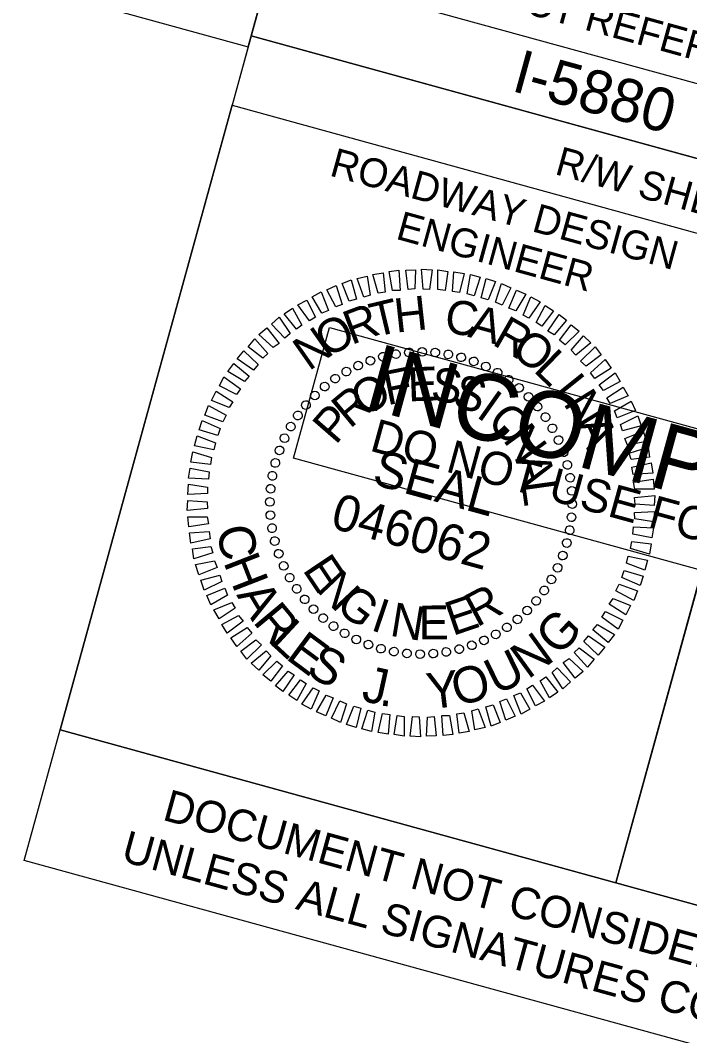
# Model space of a CAD drawing. Extents: x 1641063 to 2864602, y 841295 to 973236.
# Drawn here: x 1642843.9 to 1642960, y 842189.2 to 842365.5 of the extents above; entities that cross this region are included whole.
import ezdxf

# ---------------------------------------------------------------- set-up
doc = ezdxf.new("R2010")
doc.units = 0
for name, color, linetype in [('Default', 7, 'Continuous'), ('Old_Level_1', 7, 'Continuous'), ('Prop CMT Concrete Structures', 7, 'Continuous'), ('Prop CMT Guardrail Widen Shoulder', 7, 'Continuous'), ('Prop CMT Shoulder Point', 7, 'Continuous'), ('Prop DSN Text', 7, 'Continuous'), ('Prop Easement Construction', 7, 'Continuous')]:
    doc.layers.add(name, color=color, linetype=linetype)

msp = doc.modelspace()

# ---------------------------------------------------------------- linework, layer by layer
at = {"layer": 'Old_Level_1'}
msp.add_lwpolyline([(1642891.27, 842289.47), (1642897.51, 842312.13), (1643039.24, 842273.13), (1643033, 842250.47)], close=True, dxfattribs=at)
at = {"layer": 'Prop CMT Concrete Structures'}
for p, q in [((1642887.23, 842374.88), (1643080.1, 842321.79)), ((1642883.91, 842362.79), (1642880.6, 842350.75)), ((1642883.91, 842362.79), (1643076.79, 842309.74)), ((1642883.91, 842362.79), (1643076.79, 842309.74)), ((1642977.06, 842324.21), (1642947.23, 842215.77))]:
    msp.add_line(p, q, dxfattribs=at)
for points in [[(1641358.6, 841719.52), (1641637.16, 842731.87), (1642890.57, 842386.98), (1642850.76, 842242.29), (1643043.63, 842189.2), (1642804.85, 841321.52)], [(1642890.57, 842386.98), (1643083.47, 842333.88), (1643076.79, 842309.74), (1642883.91, 842362.79)], [(1642880.6, 842350.75), (1642977.06, 842324.21), (1642947.21, 842215.73), (1642850.76, 842242.29)], [(1642977.06, 842324.21), (1643073.47, 842297.69), (1643043.63, 842189.2), (1642947.21, 842215.73)]]:
    msp.add_lwpolyline(points, close=True, dxfattribs=at)
at = {"layer": 'Prop CMT Guardrail Widen Shoulder'}
msp.add_lwpolyline([(1642738.73, 842400.68), (1642883.38, 842360.88), (1642890.57, 842386.98), (1642745.92, 842426.79)], close=True, dxfattribs=at)
at = {"layer": 'Prop DSN Text'}
for p, q in [((1642844.53, 842219.63), (1642850.76, 842242.29)), ((1642844.53, 842219.63), (1642850.76, 842242.29)), ((1642850.76, 842242.29), (1643043.63, 842189.22)), ((1642850.76, 842242.29), (1643043.63, 842189.22)), ((1643037.4, 842166.56), (1642844.53, 842219.63)), ((1643037.4, 842166.56), (1642844.53, 842219.63))]:
    msp.add_line(p, q, dxfattribs=at)
at = {"layer": 'Prop Easement Construction'}
for p, q in [((1642906.8, 842307.08), (1642906.8, 842307.08)), ((1642909.03, 842307.58), (1642909.03, 842307.58)), ((1642911.27, 842307.87), (1642911.27, 842307.87)), ((1642913.55, 842307.94), (1642913.55, 842307.94)), ((1642915.88, 842307.77), (1642915.88, 842307.77)), ((1642918.14, 842307.52), (1642918.14, 842307.52)), ((1642920.38, 842306.99), (1642920.38, 842306.99)), ((1642902.48, 842305.59), (1642902.48, 842305.59)), ((1642904.57, 842306.41), (1642904.57, 842306.41)), ((1642922.57, 842306.27), (1642922.57, 842306.27)), ((1642924.66, 842305.36), (1642924.66, 842305.36)), ((1642898.49, 842303.32), (1642898.49, 842303.32)), ((1642900.41, 842304.5), (1642900.41, 842304.5)), ((1642926.67, 842304.36), (1642926.67, 842304.36)), ((1642896.67, 842301.9), (1642896.67, 842301.9)), ((1642928.61, 842303.1), (1642928.61, 842303.1)), ((1642930.4, 842301.67), (1642930.4, 842301.67)), ((1642894.94, 842300.4), (1642894.94, 842300.4)), ((1642932.12, 842300.15), (1642932.12, 842300.15)), ((1642893.42, 842298.69), (1642893.42, 842298.69)), ((1642933.62, 842298.42), (1642933.62, 842298.42)), ((1642891.99, 842296.9), (1642891.99, 842296.9)), ((1642935.04, 842296.59), (1642935.04, 842296.59)), ((1642890.73, 842294.95), (1642890.73, 842294.95)), ((1642936.22, 842294.67), (1642936.22, 842294.67)), ((1642889.73, 842292.94), (1642889.73, 842292.94)), ((1642937.31, 842292.61), (1642937.31, 842292.61)), ((1642888.82, 842290.85), (1642888.82, 842290.85)), ((1642938.12, 842290.51), (1642938.12, 842290.51)), ((1642888.09, 842288.66), (1642888.09, 842288.66)), ((1642938.79, 842288.29), (1642938.79, 842288.29)), ((1642887.57, 842286.42), (1642887.57, 842286.42)), ((1642939.3, 842286.05), (1642939.3, 842286.05)), ((1642887.32, 842284.17), (1642887.32, 842284.17)), ((1642939.59, 842283.82), (1642939.59, 842283.82)), ((1642887.15, 842281.83), (1642887.15, 842281.83)), ((1642913.4, 842281.69), (1642913.4, 842281.69)), ((1642939.65, 842281.54), (1642939.65, 842281.54)), ((1642887.21, 842279.55), (1642887.21, 842279.55)), ((1642939.49, 842279.21), (1642939.49, 842279.21)), ((1642887.5, 842277.32), (1642887.5, 842277.32)), ((1642939.23, 842276.95), (1642939.23, 842276.95)), ((1642888.01, 842275.08), (1642888.01, 842275.08)), ((1642938.71, 842274.71), (1642938.71, 842274.71)), ((1642888.68, 842272.86), (1642888.68, 842272.86)), ((1642937.99, 842272.52), (1642937.99, 842272.52)), ((1642889.49, 842270.76), (1642889.49, 842270.76)), ((1642937.07, 842270.43), (1642937.07, 842270.43)), ((1642890.58, 842268.7), (1642890.58, 842268.7)), ((1642936.07, 842268.42), (1642936.07, 842268.42)), ((1642891.76, 842266.78), (1642891.76, 842266.78)), ((1642934.82, 842266.48), (1642934.82, 842266.48)), ((1642893.19, 842264.95), (1642893.19, 842264.95)), ((1642933.39, 842264.68), (1642933.39, 842264.68)), ((1642894.68, 842263.22), (1642894.68, 842263.22)), ((1642931.87, 842262.97), (1642931.87, 842262.97)), ((1642896.4, 842261.7), (1642896.4, 842261.7)), ((1642930.13, 842261.47), (1642930.13, 842261.47)), ((1642898.19, 842260.27), (1642898.19, 842260.27)), ((1642928.31, 842260.05), (1642928.31, 842260.05)), ((1642900.14, 842259.01), (1642900.14, 842259.01)), ((1642902.15, 842258.01), (1642902.15, 842258.01)), ((1642924.33, 842257.78), (1642924.33, 842257.78)), ((1642926.39, 842258.87), (1642926.39, 842258.87)), ((1642904.23, 842257.1), (1642904.23, 842257.1)), ((1642906.42, 842256.38), (1642906.42, 842256.38)), ((1642908.66, 842255.86), (1642908.66, 842255.86)), ((1642917.77, 842255.79), (1642917.77, 842255.79)), ((1642920.01, 842256.29), (1642920.01, 842256.29)), ((1642922.23, 842256.96), (1642922.23, 842256.96)), ((1642910.92, 842255.6), (1642910.92, 842255.6)), ((1642913.25, 842255.43), (1642913.25, 842255.43)), ((1642915.54, 842255.5), (1642915.54, 842255.5))]:
    msp.add_line(p, q, dxfattribs=at)
for points in [[(1642903.46, 842317.43), (1642902.29, 842320.65), (1642904.07, 842321.06), (1642904.58, 842317.79)], [(1642905.95, 842318.09), (1642905.06, 842321.34), (1642906.81, 842321.65), (1642907.18, 842318.26)], [(1642908.45, 842318.58), (1642907.89, 842321.86), (1642909.56, 842322.08), (1642909.8, 842318.56)], [(1642911.14, 842318.76), (1642910.76, 842322.09), (1642912.44, 842322.15), (1642912.3, 842318.84)], [(1642913.74, 842318.79), (1642913.5, 842322.25), (1642915.31, 842322.17), (1642914.87, 842318.77)], [(1642916.32, 842318.72), (1642916.34, 842322.17), (1642918.05, 842321.9), (1642917.57, 842318.56)], [(1642918.83, 842318.4), (1642919.1, 842321.79), (1642920.87, 842321.55), (1642920.08, 842318.24)], [(1642921.42, 842318.01), (1642922.01, 842321.37), (1642923.67, 842320.89), (1642922.63, 842317.65)], [(1642898.59, 842315.71), (1642897.04, 842318.7), (1642898.68, 842319.42), (1642899.72, 842316.12)], [(1642900.91, 842316.74), (1642899.7, 842319.8), (1642901.26, 842320.43), (1642902.18, 842317.06)], [(1642923.84, 842317.33), (1642924.69, 842320.63), (1642926.34, 842320.15), (1642925.04, 842316.97)], [(1642926.33, 842316.53), (1642927.38, 842319.77), (1642928.97, 842319.04), (1642927.5, 842316.02)], [(1642896.16, 842314.66), (1642894.51, 842317.46), (1642896.04, 842318.37), (1642897.31, 842315.12)], [(1642928.66, 842315.5), (1642929.95, 842318.63), (1642931.56, 842317.95), (1642929.84, 842315.04)], [(1642931.1, 842314.28), (1642932.45, 842317.45), (1642934.07, 842316.6), (1642932.1, 842313.76)], [(1642894.04, 842313.32), (1642891.99, 842316.06), (1642893.55, 842316.9), (1642895.06, 842313.92)], [(1642933.36, 842313), (1642934.93, 842315.95), (1642936.37, 842315.04), (1642934.34, 842312.37)], [(1642889.76, 842310.31), (1642887.47, 842312.74), (1642888.8, 842313.96), (1642890.66, 842311.11)], [(1642891.77, 842311.85), (1642889.65, 842314.5), (1642891.1, 842315.53), (1642892.72, 842312.58)], [(1642935.41, 842311.51), (1642937.39, 842314.4), (1642938.65, 842313.43), (1642936.48, 842310.85)], [(1642887.72, 842308.68), (1642885.27, 842310.92), (1642886.65, 842312.08), (1642888.76, 842309.38)], [(1642937.44, 842309.96), (1642939.47, 842312.62), (1642940.86, 842311.51), (1642938.41, 842309.12)], [(1642939.47, 842308.2), (1642941.58, 842310.73), (1642942.88, 842309.48), (1642940.28, 842307.34)], [(1642885.95, 842306.81), (1642883.38, 842308.82), (1642884.55, 842310.19), (1642886.8, 842307.62)], [(1642941.1, 842306.32), (1642943.62, 842308.8), (1642944.67, 842307.4), (1642942.06, 842305.43)], [(1642884.34, 842304.74), (1642881.49, 842306.71), (1642882.66, 842308.09), (1642885.13, 842305.73)], [(1642882.75, 842302.77), (1642879.84, 842304.49), (1642880.91, 842305.89), (1642883.58, 842303.69)], [(1642942.78, 842304.27), (1642945.37, 842306.57), (1642946.4, 842305.12), (1642943.56, 842303.31)], [(1642881.37, 842300.54), (1642878.4, 842302), (1642879.18, 842303.58), (1642882.05, 842301.5)], [(1642944.31, 842302.21), (1642947.06, 842304.31), (1642947.96, 842302.78), (1642945.07, 842301.2)], [(1642945.67, 842299.97), (1642948.46, 842301.79), (1642949.37, 842300.26), (1642946.23, 842298.96)], [(1642880.09, 842298.27), (1642877.05, 842299.48), (1642877.85, 842301.12), (1642880.76, 842299.23)], [(1642879.02, 842295.8), (1642875.85, 842296.93), (1642876.5, 842298.6), (1642879.58, 842296.95)], [(1642946.98, 842297.69), (1642949.89, 842299.37), (1642950.61, 842297.73), (1642947.43, 842296.49)], [(1642947.99, 842295.32), (1642951.02, 842296.81), (1642951.61, 842295.1), (1642948.35, 842294.2)], [(1642878.14, 842293.43), (1642874.87, 842294.37), (1642875.4, 842296.02), (1642878.55, 842294.62)], [(1642877.44, 842290.91), (1642874.11, 842291.6), (1642874.55, 842293.32), (1642877.75, 842292.12)], [(1642948.78, 842292.91), (1642951.95, 842294.14), (1642952.53, 842292.38), (1642949.23, 842291.71)], [(1642949.52, 842290.34), (1642952.81, 842291.39), (1642953.07, 842289.65), (1642949.88, 842289.22)], [(1642876.84, 842288.36), (1642873.45, 842288.8), (1642873.79, 842290.55), (1642877.05, 842289.61)], [(1642876.52, 842285.85), (1642873.05, 842285.99), (1642873.34, 842287.75), (1642876.63, 842287.12)], [(1642949.98, 842287.9), (1642953.35, 842288.66), (1642953.6, 842286.87), (1642950.2, 842286.66)], [(1642950.28, 842285.29), (1642953.7, 842285.81), (1642953.86, 842284.1), (1642950.51, 842284.1)], [(1642876.35, 842283.31), (1642872.92, 842283.16), (1642873.05, 842284.96), (1642876.32, 842284.45)], [(1642876.34, 842280.72), (1642872.8, 842280.39), (1642872.92, 842282.14), (1642876.26, 842281.87)], [(1642950.46, 842282.65), (1642954, 842282.98), (1642953.88, 842281.23), (1642950.55, 842281.5)], [(1642876.53, 842278.08), (1642873.1, 842277.56), (1642872.94, 842279.27), (1642876.29, 842279.27)], [(1642950.45, 842280.06), (1642953.89, 842280.21), (1642953.75, 842278.41), (1642950.48, 842278.92)], [(1642950.28, 842277.52), (1642953.75, 842277.38), (1642953.46, 842275.62), (1642950.17, 842276.25)], [(1642876.83, 842275.47), (1642873.45, 842274.71), (1642873.21, 842276.5), (1642876.61, 842276.71)], [(1642877.28, 842273.03), (1642873.99, 842271.98), (1642873.73, 842273.72), (1642876.92, 842274.15)], [(1642949.96, 842275.01), (1642953.36, 842274.57), (1642953.02, 842272.82), (1642949.75, 842273.77)], [(1642878.03, 842270.46), (1642874.85, 842269.23), (1642874.28, 842270.99), (1642877.58, 842271.66)], [(1642949.36, 842272.46), (1642952.69, 842271.77), (1642952.25, 842270.05), (1642949.05, 842271.25)], [(1642948.66, 842269.94), (1642951.93, 842269), (1642951.4, 842267.35), (1642948.25, 842268.75)], [(1642878.81, 842268.05), (1642875.78, 842266.56), (1642875.2, 842268.27), (1642878.45, 842269.17)], [(1642879.82, 842265.68), (1642876.91, 842264), (1642876.2, 842265.64), (1642879.37, 842266.88)], [(1642947.78, 842267.58), (1642950.95, 842266.44), (1642950.3, 842264.77), (1642947.22, 842266.43)], [(1642946.72, 842265.1), (1642949.75, 842263.89), (1642948.96, 842262.25), (1642946.04, 842264.14)], [(1642881.13, 842263.4), (1642878.34, 842261.58), (1642877.44, 842263.11), (1642880.58, 842264.41)], [(1642945.43, 842262.83), (1642948.41, 842261.37), (1642947.62, 842259.79), (1642944.76, 842261.87)], [(1642882.5, 842261.16), (1642879.74, 842259.06), (1642878.84, 842260.59), (1642881.73, 842262.17)], [(1642884.02, 842259.1), (1642881.43, 842256.8), (1642880.4, 842258.25), (1642883.24, 842260.06)], [(1642944.05, 842260.6), (1642946.96, 842258.88), (1642945.9, 842257.48), (1642943.22, 842259.68)], [(1642885.71, 842257.05), (1642883.18, 842254.57), (1642882.13, 842255.97), (1642884.75, 842257.94)], [(1642942.47, 842258.63), (1642945.31, 842256.66), (1642944.15, 842255.28), (1642941.67, 842257.64)], [(1642887.33, 842255.17), (1642885.22, 842252.64), (1642883.92, 842253.89), (1642886.52, 842256.03)], [(1642940.86, 842256.56), (1642943.42, 842254.55), (1642942.26, 842253.18), (1642940, 842255.75)], [(1642889.36, 842253.41), (1642887.33, 842250.75), (1642885.94, 842251.86), (1642888.39, 842254.25)], [(1642939.08, 842254.69), (1642941.53, 842252.45), (1642940.15, 842251.29), (1642938.04, 842253.99)], [(1642891.39, 842251.86), (1642889.41, 842248.97), (1642888.15, 842249.94), (1642890.32, 842252.52)], [(1642937.04, 842253.06), (1642939.34, 842250.63), (1642938, 842249.41), (1642936.14, 842252.26)], [(1642893.44, 842250.37), (1642891.87, 842247.42), (1642890.43, 842248.33), (1642892.47, 842251)], [(1642935.03, 842251.52), (1642937.16, 842248.87), (1642935.7, 842247.84), (1642934.09, 842250.79)], [(1642895.7, 842249.09), (1642894.35, 842245.92), (1642892.73, 842246.77), (1642894.7, 842249.61)], [(1642930.64, 842248.71), (1642932.29, 842245.91), (1642930.77, 842245), (1642929.49, 842248.25)], [(1642932.76, 842250.05), (1642934.81, 842247.31), (1642933.25, 842246.47), (1642931.75, 842249.45)], [(1642898.14, 842247.87), (1642896.85, 842244.74), (1642895.25, 842245.42), (1642896.96, 842248.33)], [(1642900.47, 842246.84), (1642899.42, 842243.6), (1642897.83, 842244.33), (1642899.3, 842247.35)], [(1642928.21, 842247.66), (1642929.76, 842244.67), (1642928.12, 842243.96), (1642927.08, 842247.25)], [(1642902.96, 842246.04), (1642902.12, 842242.74), (1642900.46, 842243.22), (1642901.76, 842246.4)], [(1642905.38, 842245.36), (1642904.79, 842242.01), (1642903.13, 842242.48), (1642904.18, 842245.72)], [(1642907.98, 842244.97), (1642907.7, 842241.58), (1642905.93, 842241.82), (1642906.72, 842245.13)], [(1642920.85, 842245.28), (1642921.74, 842242.03), (1642919.99, 842241.72), (1642919.62, 842245.11)], [(1642923.34, 842245.94), (1642924.51, 842242.72), (1642922.74, 842242.31), (1642922.22, 842245.58)], [(1642925.89, 842246.63), (1642927.11, 842243.57), (1642925.54, 842242.94), (1642924.62, 842246.31)], [(1642910.49, 842244.65), (1642910.46, 842241.2), (1642908.75, 842241.47), (1642909.23, 842244.81)], [(1642913.06, 842244.58), (1642913.31, 842241.12), (1642911.49, 842241.2), (1642911.93, 842244.6)], [(1642915.66, 842244.61), (1642916.05, 842241.28), (1642914.36, 842241.22), (1642914.51, 842244.53)], [(1642918.35, 842244.79), (1642918.91, 842241.51), (1642917.24, 842241.3), (1642917.01, 842244.81)]]:
    msp.add_lwpolyline(points, close=True, dxfattribs=at)
for centre, major_axis in [((1642911.29, 842307.83), (-0.061, 0.751)), ((1642913.58, 842307.91), (0.005, 0.753)), ((1642915.86, 842307.8), (0.071, 0.75)), ((1642904.6, 842306.39), (-0.253, 0.709)), ((1642906.78, 842307.06), (-0.19, 0.729)), ((1642909.02, 842307.54), (-0.126, 0.742)), ((1642918.13, 842307.48), (0.136, 0.741)), ((1642920.36, 842306.97), (0.2, 0.726)), ((1642922.54, 842306.27), (0.262, 0.706)), ((1642900.44, 842304.49), (-0.372, 0.655)), ((1642902.48, 842305.53), (-0.314, 0.685)), ((1642924.65, 842305.38), (0.323, 0.68)), ((1642926.67, 842304.31), (0.381, 0.65)), ((1642898.5, 842303.27), (-0.428, 0.62)), ((1642928.59, 842303.07), (0.436, 0.614)), ((1642896.68, 842301.89), (-0.48, 0.58)), ((1642930.4, 842301.66), (0.488, 0.574)), ((1642894.98, 842300.36), (-0.529, 0.536)), ((1642932.07, 842300.11), (0.536, 0.529)), ((1642893.42, 842298.68), (-0.574, 0.488)), ((1642933.61, 842298.41), (0.58, 0.48)), ((1642892.02, 842296.87), (-0.614, 0.436)), ((1642934.99, 842296.58), (0.62, 0.428)), ((1642890.78, 842294.95), (-0.65, 0.381)), ((1642936.2, 842294.65), (0.655, 0.372)), ((1642889.71, 842292.93), (-0.68, 0.323)), ((1642937.25, 842292.61), (0.685, 0.314)), ((1642888.82, 842290.82), (-0.706, 0.262)), ((1642938.11, 842290.49), (0.709, 0.253)), ((1642888.11, 842288.64), (-0.726, 0.2)), ((1642938.78, 842288.3), (0.729, 0.19)), ((1642887.6, 842286.41), (-0.741, 0.136)), ((1642939.26, 842286.07), (0.742, 0.126)), ((1642887.29, 842284.15), (-0.75, 0.071)), ((1642939.54, 842283.79), (0.751, 0.061)), ((1642887.17, 842281.86), (-0.753, 0.005)), ((1642939.63, 842281.51), (0.753, -0.005)), ((1642887.26, 842279.58), (-0.751, -0.061)), ((1642939.51, 842279.22), (0.75, -0.071)), ((1642887.54, 842277.31), (-0.742, -0.126)), ((1642939.2, 842276.96), (0.741, -0.136)), ((1642888.02, 842275.07), (-0.729, -0.19)), ((1642938.69, 842274.73), (0.726, -0.2)), ((1642888.69, 842272.88), (-0.709, -0.253)), ((1642937.99, 842272.55), (0.706, -0.262)), ((1642889.56, 842270.76), (-0.685, -0.314)), ((1642937.1, 842270.44), (0.68, -0.323)), ((1642890.6, 842268.72), (-0.655, -0.372)), ((1642936.03, 842268.42), (0.65, -0.381)), ((1642891.82, 842266.79), (-0.62, -0.428)), ((1642934.78, 842266.5), (0.614, -0.436)), ((1642893.2, 842264.96), (-0.58, -0.48)), ((1642933.38, 842264.69), (0.574, -0.488)), ((1642894.73, 842263.26), (-0.536, -0.529)), ((1642931.82, 842263.01), (0.529, -0.536)), ((1642896.41, 842261.71), (-0.488, -0.574)), ((1642898.21, 842260.3), (-0.436, -0.614)), ((1642928.3, 842260.1), (0.428, -0.62)), ((1642930.12, 842261.48), (0.48, -0.58)), ((1642900.13, 842259.06), (-0.381, -0.65)), ((1642926.36, 842258.88), (0.372, -0.655)), ((1642902.16, 842257.99), (-0.323, -0.68)), ((1642904.26, 842257.1), (-0.262, -0.706)), ((1642922.2, 842256.98), (0.253, -0.709)), ((1642924.32, 842257.84), (0.314, -0.685)), ((1642906.44, 842256.4), (-0.2, -0.726)), ((1642908.67, 842255.89), (-0.136, -0.741)), ((1642910.94, 842255.57), (-0.071, -0.75)), ((1642913.22, 842255.46), (-0.005, -0.753)), ((1642915.51, 842255.54), (0.061, -0.751)), ((1642917.78, 842255.83), (0.126, -0.742)), ((1642920.02, 842256.31), (0.19, -0.729))]:
    msp.add_ellipse(centre, major_axis=major_axis, ratio=0.999708, dxfattribs=at)

# ---------------------------------------------------------------- texts
at = {"layer": 'Default'}
for s, rotation, p in [('C', 281.8134, (1642877.83, 842277.23)), ('H', 291.2571, (1642879.04, 842271.46)), ('A', 301.0969, (1642881.29, 842265.73)), ('R', 309.8096, (1642884.07, 842261.05)), ('G', 46.4133, (1642937.26, 842254.9)), ('L', 317.1818, (1642886.96, 842257.46)), ('E', 323.366, (1642889.72, 842254.75)), ('N', 35.8424, (1642931.94, 842250.98)), ('S', 330.3726, (1642893.18, 842252.06)), ('U', 26.0482, (1642926.45, 842248.27)), ('J', 347.6456, (1642902.88, 842247.39)), ('Y', 6.8561, (1642914.75, 842245.84)), ('O', 14.6548, (1642919.6, 842246.35)), ('.', 352.8275, (1642906.02, 842246.58))]:
    msp.add_text(s, height=6.27, rotation=rotation, dxfattribs=at).set_placement(p)
at = {"layer": 'Old_Level_1'}
for s, height, p in [('INCOMPLETE PLANS', 11.52, (1642903.01, 842298.38)), ('DO NOT USE FOR R/W ACQUISITION', 5.76, (1642904.29, 842290.82))]:
    msp.add_text(s, height=height, rotation=344.6135, dxfattribs=at).set_placement(p)
at = {"layer": 'Prop CMT Concrete Structures'}
for s, height, p in [('PROJECT REFERENCE NO.', 5.0001, (1642909.66, 842372.68)), ('ROADWAY DESIGN', 5.0001, (1642897.34, 842338.57)), ('R/W SHEET NO.', 5.0001, (1642936.43, 842338.81)), ('ENGINEER', 5, (1642908.83, 842327.59))]:
    msp.add_text(s, height=height, rotation=344.6135, dxfattribs=at).set_placement(p)
at = {"layer": 'Prop CMT Shoulder Point'}
msp.add_text('I-5880', height=7.5, rotation=344.6135, dxfattribs=at).set_placement((1642928.87, 842353.28))
at = {"layer": 'Prop DSN Text'}
for s, p in [('DOCUMENT NOT CONSIDERED FINAL', (1642868.33, 842226.73)), ('DOCUMENT NOT CONSIDERED FINAL', (1642868.33, 842226.73)), ('UNLESS ALL SIGNATURES COMPLETED', (1642861.11, 842219.59)), ('UNLESS ALL SIGNATURES COMPLETED', (1642861.11, 842219.59))]:
    msp.add_text(s, height=5.5, rotation=344.6135, dxfattribs=at).set_placement(p)
at = {"layer": 'Prop Easement Construction'}
for s, height, rotation, p in [('H', 5.9, 6.233, (1642909.05, 842311.25)), ('R', 5.9, 20.634, (1642901.32, 842309.08)), ('T', 5.9, 13.4333, (1642905.33, 842310.42)), ('C', 5.9, 351.8334, (1642917.27, 842311.3)), ('A', 5.9, 344.6338, (1642921.35, 842310.58)), ('O', 5.9, 27.8352, (1642897.02, 842306.83)), ('R', 5.9, 330.2346, (1642925.55, 842309.28)), ('N', 5.9, 35.037, (1642893.93, 842304.49)), ('O', 5.9, 323.0347, (1642928.75, 842307.65)), ('L', 5.9, 315.8344, (1642932.73, 842304.64)), ('F', 5.9, 11.5805, (1642907.54, 842298.63)), ('E', 5.9, 2.2246, (1642911.18, 842299.31)), ('S', 5.9, 352.8691, (1642914.94, 842299.48)), ('O', 5.9, 30.2947, (1642903.43, 842296.5)), ('S', 5.9, 343.5139, (1642918.6, 842298.6)), ('I', 5.9, 308.6336, (1642936.21, 842301.15)), ('R', 5.9, 39.6532, (1642901.03, 842294.47)), ('N', 5.9, 301.4324, (1642937.98, 842299.02)), ('I', 5.9, 324.8031, (1642922.78, 842296.77)), ('P', 5.9, 49.0124, (1642898.57, 842291.64)), ('O', 5.9, 315.447, (1642924.62, 842295.54)), ('N', 5.9, 306.0901, (1642927.49, 842292.65)), ('A', 5.9, 294.2307, (1642940.21, 842295.27)), ('SEAL', 6.273, 344.6135, (1642904.7, 842285)), ('A', 5.9, 287.3738, (1642929.71, 842289.27)), ('L', 5.9, 278.0144, (1642930.78, 842285.27)), ('046062', 6.275, 344.6135, (1642897.46, 842277.44)), ('E', 5.9, 303.8904, (1642892.72, 842270.09)), ('N', 5.9, 313.2475, (1642895.06, 842266.58)), ('G', 5.9, 322.6037, (1642898.32, 842263.31)), ('R', 5.9, 28.0949, (1642923.07, 842260.04)), ('I', 5.9, 341.3147, (1642904.47, 842259.69)), ('E', 5.9, 18.7376, (1642918.87, 842258.58)), ('N', 5.9, 350.6699, (1642907.82, 842258.66)), ('E', 5.9, 0.0253, (1642912.99, 842257.99))]:
    msp.add_text(s, height=height, rotation=rotation, dxfattribs=at).set_placement(p)

doc.saveas('drawing.dxf')
